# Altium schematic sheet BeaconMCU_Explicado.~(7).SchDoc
size A4
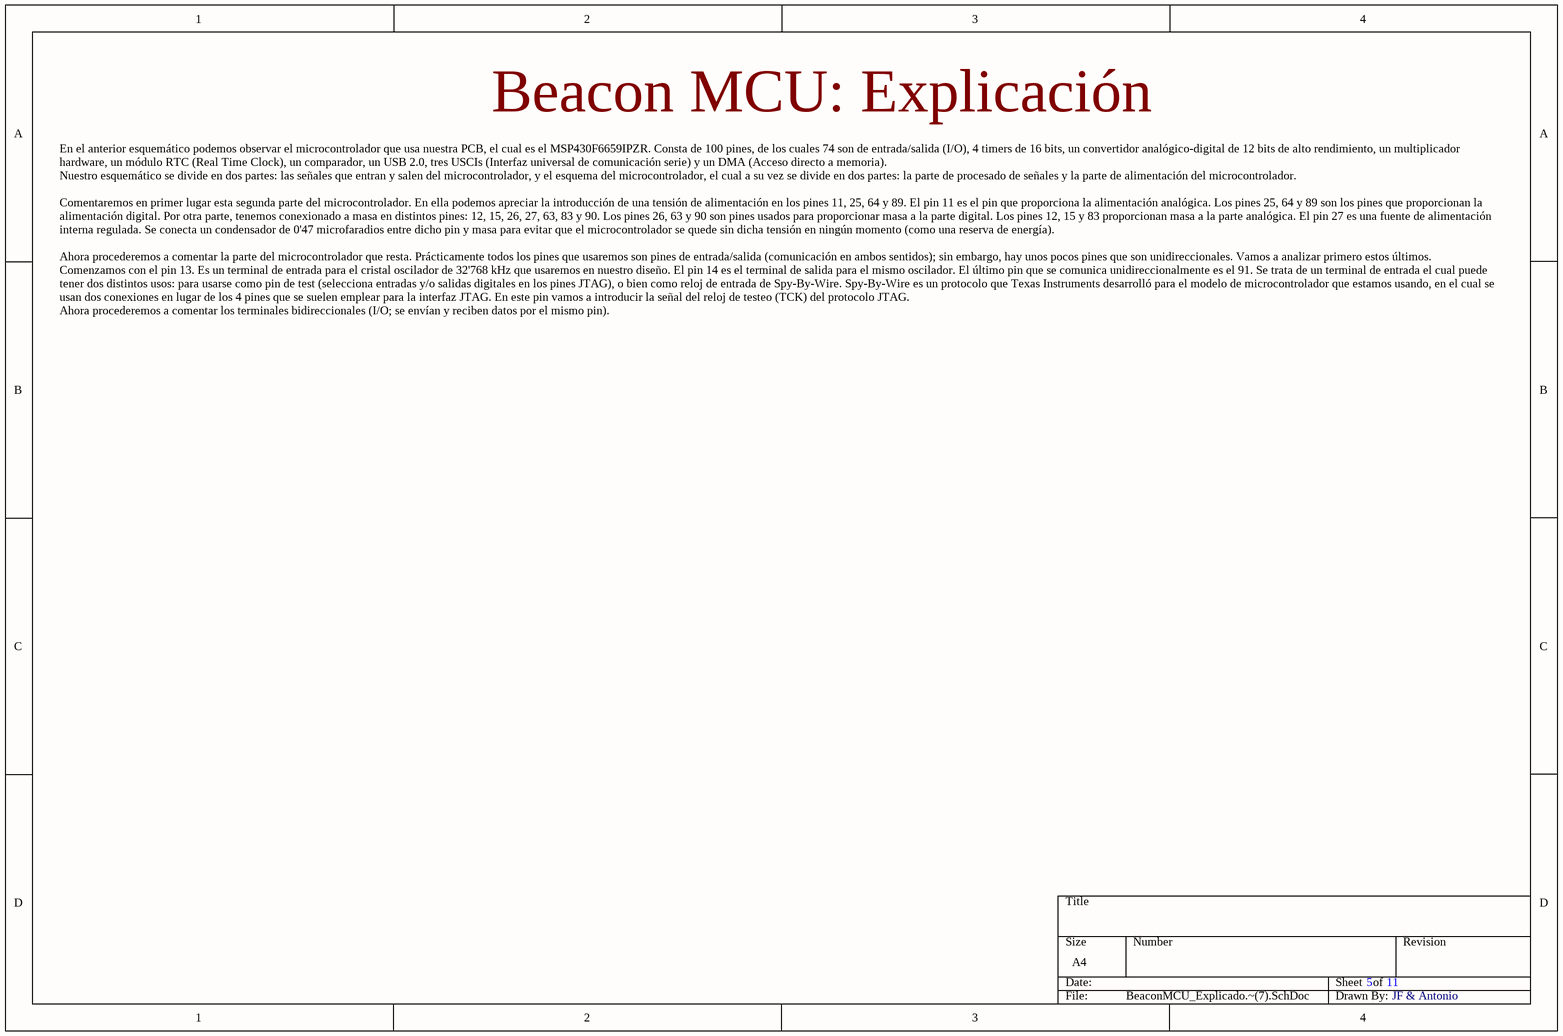
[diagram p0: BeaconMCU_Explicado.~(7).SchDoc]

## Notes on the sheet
- Beacon MCU: Explicación
- En el anterior esquemático podemos observar el microcontrolador que usa nuestra PCB, el cual es el MSP430F6659IPZR. Consta de 100 pines, de los cuales 74 son de entrada/salida (I/O), 4 timers de 16 bits, un convertidor analógico-digital de 12 bits de alto rendimiento, un multiplicador hardware, un módulo RTC (Real Time Clock), un comparador, un USB 2.0, tres USCIs (Interfaz universal de comunicación serie) y un DMA (Acceso directo a memoria).
  Nuestro esquemático se divide en dos partes: las señales que entran y salen del microcontrolador, y el esquema del microcontrolador, el cual a su vez se divide en dos partes: la parte de procesado de señales y la parte de alimentación del microcontrolador.
  Comentaremos en primer lugar esta segunda parte del microcontrolador. En ella podemos apreciar la introducción de una tensión de alimentación en los pines 11, 25, 64 y 89. El pin 11 es el pin que proporciona la alimentación analógica. Los pines 25, 64 y 89 son los pines que proporcionan la alimentación digital. Por otra parte, tenemos conexionado a masa en distintos pines: 12, 15, 26, 27, 63, 83 y 90. Los pines 26, 63 y 90 son pines usados para proporcionar masa a la parte digital. Los pines 12, 15 y 83 proporcionan masa a la parte analógica. El pin 27 es una fuente de alimentación interna regulada. Se conecta un condensador de 0'47 microfaradios entre dicho pin y masa para evitar que el microcontrolador se quede sin dicha tensión en ningún momento (como una reserva de energía).
  Ahora procederemos a comentar la parte del microcontrolador que resta. Prácticamente todos los pines que usaremos son pines de entrada/salida (comunicación en ambos sentidos); sin embargo, hay unos pocos pines que son unidireccionales. Vamos a analizar primero estos últimos.
  Comenzamos con el pin 13. Es un terminal de entrada para el cristal oscilador de 32'768 kHz que usaremos en nuestro diseño. El pin 14 es el terminal de salida para el mismo oscilador. El último pin que se comunica unidireccionalmente es el 91. Se trata de un terminal de entrada el cual puede tener dos distintos usos: para usarse como pin de test (selecciona entradas y/o salidas digitales en los pines JTAG), o bien como reloj de entrada de Spy-By-Wire. Spy-By-Wire es un protocolo que Texas Instruments desarrolló para el modelo de microcontrolador que estamos usando, en el cual se usan dos conexiones en lugar de los 4 pines que se suelen emplear para la interfaz JTAG. En este pin vamos a introducir la señal del reloj de testeo (TCK) del protocolo JTAG.
  Ahora procederemos a comentar los terminales bidireccionales (I/O; se envían y reciben datos por el mismo pin).
- 5
- 11
- JF & Antonio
